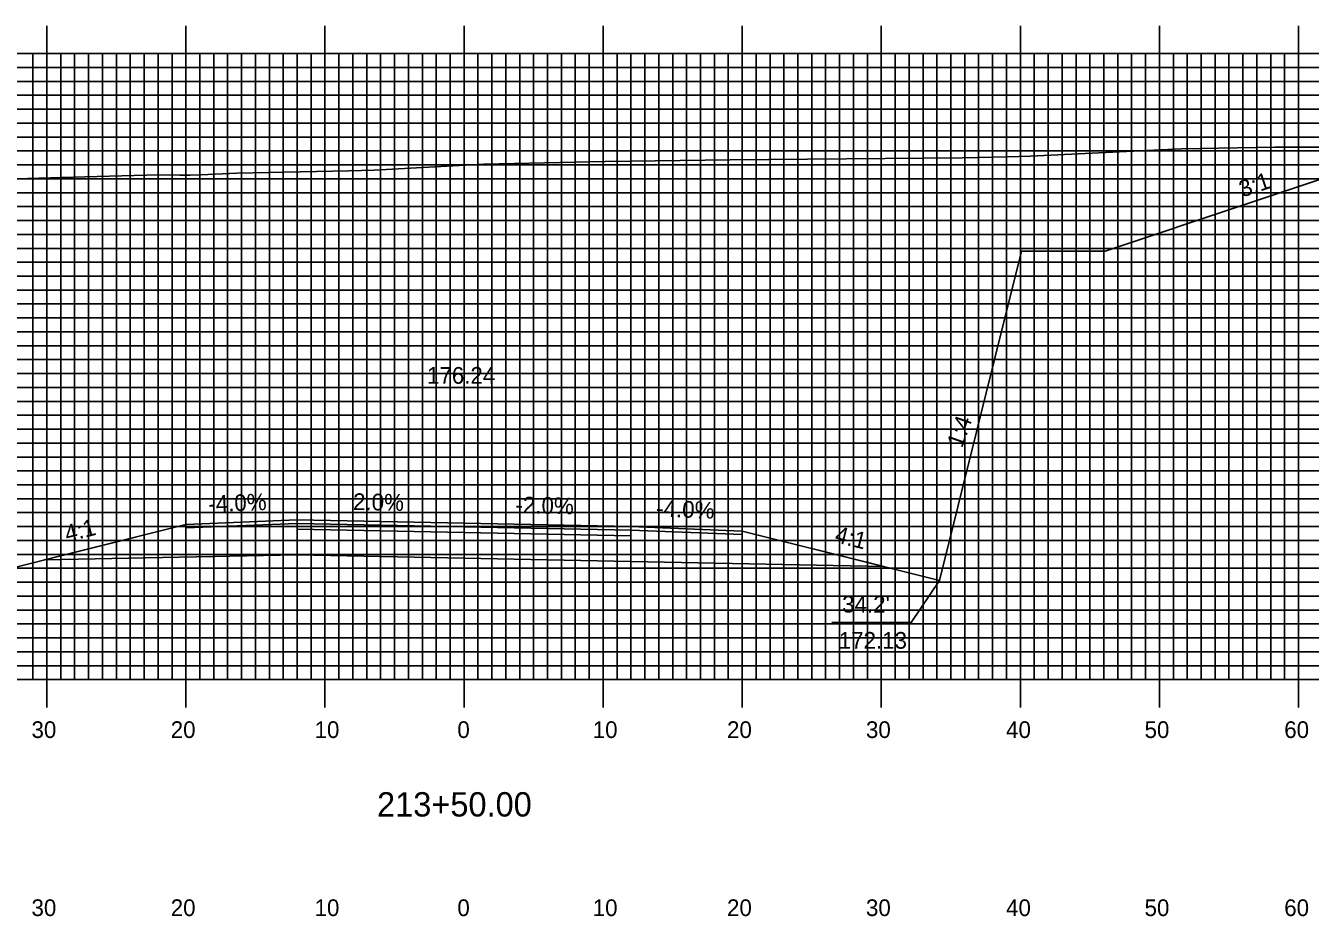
# Model space of a CAD drawing. Extents: x 1795633 to 1795976, y 442591 to 442811.
# Drawn here: x 1795767.4 to 1795859.7, y 442656.6 to 442720.7 of the extents above; entities that cross this region are included whole.
import ezdxf

# ---------------------------------------------------------------- set-up
doc = ezdxf.new("R2010")
doc.units = 0
for name, color, linetype in [('ANNOTATION', 7, 'Continuous'), ('D_Roadway_Centerline', 7, 'Continuous'), ('D_Roadway_Centerline_Text', 7, 'Continuous'), ('D_Roadway_Edge_Shoulder', 7, 'Continuous'), ('D_Roadway_Edge_TW', 7, 'Continuous'), ('D_Roadway_Pavement', 7, 'Continuous'), ('D_Roadway_SlopeLines', 7, 'Continuous'), ('D_Roadway_SubGrade', 7, 'Continuous'), ('H_V ANNOTATION', 7, 'Continuous'), ('MAJOR', 7, 'Continuous'), ('MINOR', 7, 'Continuous'), ('S_Roadway_Centerline', 7, 'Continuous')]:
    doc.layers.add(name, color=color, linetype=linetype)

msp = doc.modelspace()

# ---------------------------------------------------------------- linework, layer by layer
at = {"layer": 'ANNOTATION'}
msp.add_lwpolyline([(1795825.33, 442677.758), (1795831.021, 442677.758), (1795833.053, 442680.798)], dxfattribs=at)
at = {"layer": 'D_Roadway_Edge_Shoulder'}
for points in [[(1795786.879, 442685.142), (1795778.879, 442684.822), (1795778.879, 442684.572), (1795786.879, 442684.892)], [(1795810.879, 442684.662), (1795818.879, 442684.342), (1795818.879, 442684.092), (1795810.879, 442684.412)]]:
    msp.add_lwpolyline(points, close=True, dxfattribs=at)
at = {"layer": 'D_Roadway_Edge_TW'}
msp.add_lwpolyline([(1795786.879, 442684.892), (1795786.879, 442685.142), (1795798.879, 442684.902), (1795810.879, 442684.662), (1795810.879, 442684.412), (1795798.879, 442684.652)], close=True, dxfattribs=at)
at = {"layer": 'D_Roadway_Pavement'}
msp.add_lwpolyline([(1795786.879, 442684.475), (1795786.879, 442684.892), (1795798.879, 442684.652), (1795810.879, 442684.412), (1795810.879, 442683.995), (1795798.879, 442684.235)], close=True, dxfattribs=at)
at = {"layer": 'D_Roadway_SlopeLines'}
msp.add_line((1795833.053, 442680.798), (1795837.071, 442696.871), dxfattribs=at)
for points in [[(1795837.071, 442696.871), (1795838.97, 442704.465), (1795844.97, 442704.465), (1795865.487, 442711.304)], [(1795778.879, 442684.822), (1795764.705, 442681.278)], [(1795818.879, 442684.342), (1795833.053, 442680.798)]]:
    msp.add_lwpolyline(points, dxfattribs=at)
at = {"layer": 'D_Roadway_SubGrade'}
msp.add_lwpolyline([(1795786.879, 442682.642), (1795768.705, 442682.278), (1795778.879, 442684.822), (1795778.879, 442684.572), (1795786.879, 442684.892), (1795798.879, 442684.652), (1795810.879, 442684.412), (1795818.879, 442684.092), (1795818.879, 442684.342), (1795829.053, 442681.798), (1795810.879, 442682.162), (1795798.879, 442682.402)], close=True, dxfattribs=at)
at = {"layer": 'MAJOR'}
for p, q in [((1795768.879, 442720.669), (1795768.879, 442718.665)), ((1795778.879, 442720.669), (1795778.879, 442718.665)), ((1795788.879, 442720.669), (1795788.879, 442718.665)), ((1795798.879, 442720.669), (1795798.879, 442718.665)), ((1795808.879, 442720.669), (1795808.879, 442718.665)), ((1795818.879, 442720.669), (1795818.879, 442718.665)), ((1795828.879, 442720.669), (1795828.879, 442718.665)), ((1795838.879, 442720.669), (1795838.879, 442718.665)), ((1795848.879, 442720.669), (1795848.879, 442718.665)), ((1795858.879, 442720.669), (1795858.879, 442718.665)), ((1795658.879, 442718.665), (1795938.879, 442718.665)), ((1795658.879, 442718.665), (1795938.879, 442718.665)), ((1795768.879, 442673.665), (1795768.879, 442718.665)), ((1795778.879, 442673.665), (1795778.879, 442718.665)), ((1795788.879, 442673.665), (1795788.879, 442718.665)), ((1795798.879, 442673.665), (1795798.879, 442718.665)), ((1795808.879, 442673.665), (1795808.879, 442718.665)), ((1795818.879, 442673.665), (1795818.879, 442718.665)), ((1795828.879, 442673.665), (1795828.879, 442718.665)), ((1795838.879, 442673.665), (1795838.879, 442718.665)), ((1795848.879, 442673.665), (1795848.879, 442718.665)), ((1795858.879, 442673.665), (1795858.879, 442718.665)), ((1795658.879, 442713.665), (1795938.879, 442713.665)), ((1795658.879, 442708.665), (1795938.879, 442708.665)), ((1795658.879, 442703.665), (1795938.879, 442703.665)), ((1795658.879, 442698.665), (1795938.879, 442698.665)), ((1795658.879, 442693.665), (1795938.879, 442693.665)), ((1795658.879, 442688.665), (1795938.879, 442688.665)), ((1795658.879, 442683.665), (1795938.879, 442683.665)), ((1795658.879, 442678.665), (1795938.879, 442678.665)), ((1795658.879, 442673.665), (1795938.879, 442673.665)), ((1795658.879, 442673.665), (1795938.879, 442673.665)), ((1795768.879, 442671.661), (1795768.879, 442673.665)), ((1795778.879, 442671.661), (1795778.879, 442673.665)), ((1795788.879, 442671.661), (1795788.879, 442673.665)), ((1795798.879, 442671.661), (1795798.879, 442673.665)), ((1795808.879, 442671.661), (1795808.879, 442673.665)), ((1795818.879, 442671.661), (1795818.879, 442673.665)), ((1795828.879, 442671.661), (1795828.879, 442673.665)), ((1795838.879, 442671.661), (1795838.879, 442673.665)), ((1795848.879, 442671.661), (1795848.879, 442673.665)), ((1795858.879, 442671.661), (1795858.879, 442673.665))]:
    msp.add_line(p, q, dxfattribs=at)
at = {"layer": 'MINOR'}
for p, q in [((1795767.879, 442673.665), (1795767.879, 442718.665)), ((1795769.879, 442673.665), (1795769.879, 442718.665)), ((1795770.879, 442673.665), (1795770.879, 442718.665)), ((1795771.879, 442673.665), (1795771.879, 442718.665)), ((1795772.879, 442673.665), (1795772.879, 442718.665)), ((1795773.879, 442673.665), (1795773.879, 442718.665)), ((1795774.879, 442673.665), (1795774.879, 442718.665)), ((1795775.879, 442673.665), (1795775.879, 442718.665)), ((1795776.879, 442673.665), (1795776.879, 442718.665)), ((1795777.879, 442673.665), (1795777.879, 442718.665)), ((1795779.879, 442673.665), (1795779.879, 442718.665)), ((1795780.879, 442673.665), (1795780.879, 442718.665)), ((1795781.879, 442673.665), (1795781.879, 442718.665)), ((1795782.879, 442673.665), (1795782.879, 442718.665)), ((1795783.879, 442673.665), (1795783.879, 442718.665)), ((1795784.879, 442673.665), (1795784.879, 442718.665)), ((1795785.879, 442673.665), (1795785.879, 442718.665)), ((1795786.879, 442673.665), (1795786.879, 442718.665)), ((1795787.879, 442673.665), (1795787.879, 442718.665)), ((1795789.879, 442673.665), (1795789.879, 442718.665)), ((1795790.879, 442673.665), (1795790.879, 442718.665)), ((1795791.879, 442673.665), (1795791.879, 442718.665)), ((1795792.879, 442673.665), (1795792.879, 442718.665)), ((1795793.879, 442673.665), (1795793.879, 442718.665)), ((1795794.879, 442673.665), (1795794.879, 442718.665)), ((1795795.879, 442673.665), (1795795.879, 442718.665)), ((1795796.879, 442673.665), (1795796.879, 442718.665)), ((1795797.879, 442673.665), (1795797.879, 442718.665)), ((1795799.879, 442673.665), (1795799.879, 442718.665)), ((1795800.879, 442673.665), (1795800.879, 442718.665)), ((1795801.879, 442673.665), (1795801.879, 442718.665)), ((1795802.879, 442673.665), (1795802.879, 442718.665)), ((1795803.879, 442673.665), (1795803.879, 442718.665)), ((1795804.879, 442673.665), (1795804.879, 442718.665)), ((1795805.879, 442673.665), (1795805.879, 442718.665)), ((1795806.879, 442673.665), (1795806.879, 442718.665)), ((1795807.879, 442673.665), (1795807.879, 442718.665)), ((1795809.879, 442673.665), (1795809.879, 442718.665)), ((1795810.879, 442673.665), (1795810.879, 442718.665)), ((1795811.879, 442673.665), (1795811.879, 442718.665)), ((1795812.879, 442673.665), (1795812.879, 442718.665)), ((1795813.879, 442673.665), (1795813.879, 442718.665)), ((1795814.879, 442673.665), (1795814.879, 442718.665)), ((1795815.879, 442673.665), (1795815.879, 442718.665)), ((1795816.879, 442673.665), (1795816.879, 442718.665)), ((1795817.879, 442673.665), (1795817.879, 442718.665)), ((1795819.879, 442673.665), (1795819.879, 442718.665)), ((1795820.879, 442673.665), (1795820.879, 442718.665)), ((1795821.879, 442673.665), (1795821.879, 442718.665)), ((1795822.879, 442673.665), (1795822.879, 442718.665)), ((1795823.879, 442673.665), (1795823.879, 442718.665)), ((1795824.879, 442673.665), (1795824.879, 442718.665)), ((1795825.879, 442673.665), (1795825.879, 442718.665)), ((1795826.879, 442673.665), (1795826.879, 442718.665)), ((1795827.879, 442673.665), (1795827.879, 442718.665)), ((1795829.879, 442673.665), (1795829.879, 442718.665)), ((1795830.879, 442673.665), (1795830.879, 442718.665)), ((1795831.879, 442673.665), (1795831.879, 442718.665)), ((1795832.879, 442673.665), (1795832.879, 442718.665)), ((1795833.879, 442673.665), (1795833.879, 442718.665)), ((1795834.879, 442673.665), (1795834.879, 442718.665)), ((1795835.879, 442673.665), (1795835.879, 442718.665)), ((1795836.879, 442673.665), (1795836.879, 442718.665)), ((1795837.879, 442673.665), (1795837.879, 442718.665)), ((1795839.879, 442673.665), (1795839.879, 442718.665)), ((1795840.879, 442673.665), (1795840.879, 442718.665)), ((1795841.879, 442673.665), (1795841.879, 442718.665)), ((1795842.879, 442673.665), (1795842.879, 442718.665)), ((1795843.879, 442673.665), (1795843.879, 442718.665)), ((1795844.879, 442673.665), (1795844.879, 442718.665)), ((1795845.879, 442673.665), (1795845.879, 442718.665)), ((1795846.879, 442673.665), (1795846.879, 442718.665)), ((1795847.879, 442673.665), (1795847.879, 442718.665)), ((1795849.879, 442673.665), (1795849.879, 442718.665)), ((1795850.879, 442673.665), (1795850.879, 442718.665)), ((1795851.879, 442673.665), (1795851.879, 442718.665)), ((1795852.879, 442673.665), (1795852.879, 442718.665)), ((1795853.879, 442673.665), (1795853.879, 442718.665)), ((1795854.879, 442673.665), (1795854.879, 442718.665)), ((1795855.879, 442673.665), (1795855.879, 442718.665)), ((1795856.879, 442673.665), (1795856.879, 442718.665)), ((1795857.879, 442673.665), (1795857.879, 442718.665)), ((1795658.879, 442717.665), (1795938.879, 442717.665)), ((1795658.879, 442716.665), (1795938.879, 442716.665)), ((1795658.879, 442715.665), (1795938.879, 442715.665)), ((1795658.879, 442714.665), (1795938.879, 442714.665)), ((1795658.879, 442712.665), (1795938.879, 442712.665)), ((1795658.879, 442711.665), (1795938.879, 442711.665)), ((1795658.879, 442710.665), (1795938.879, 442710.665)), ((1795658.879, 442709.665), (1795938.879, 442709.665)), ((1795658.879, 442707.665), (1795938.879, 442707.665)), ((1795658.879, 442706.665), (1795938.879, 442706.665)), ((1795658.879, 442705.665), (1795938.879, 442705.665)), ((1795658.879, 442704.665), (1795938.879, 442704.665)), ((1795658.879, 442702.665), (1795938.879, 442702.665)), ((1795658.879, 442701.665), (1795938.879, 442701.665)), ((1795658.879, 442700.665), (1795938.879, 442700.665)), ((1795658.879, 442699.665), (1795938.879, 442699.665)), ((1795658.879, 442697.665), (1795938.879, 442697.665)), ((1795658.879, 442696.665), (1795938.879, 442696.665)), ((1795658.879, 442695.665), (1795938.879, 442695.665)), ((1795658.879, 442694.665), (1795938.879, 442694.665)), ((1795658.879, 442692.665), (1795938.879, 442692.665)), ((1795658.879, 442691.665), (1795938.879, 442691.665)), ((1795658.879, 442690.665), (1795938.879, 442690.665)), ((1795658.879, 442689.665), (1795938.879, 442689.665)), ((1795658.879, 442687.665), (1795938.879, 442687.665)), ((1795658.879, 442686.665), (1795938.879, 442686.665)), ((1795658.879, 442685.665), (1795938.879, 442685.665)), ((1795658.879, 442684.665), (1795938.879, 442684.665)), ((1795658.879, 442682.665), (1795938.879, 442682.665)), ((1795658.879, 442681.665), (1795938.879, 442681.665)), ((1795658.879, 442680.665), (1795938.879, 442680.665)), ((1795658.879, 442679.665), (1795938.879, 442679.665)), ((1795658.879, 442677.665), (1795938.879, 442677.665)), ((1795658.879, 442676.665), (1795938.879, 442676.665)), ((1795658.879, 442675.665), (1795938.879, 442675.665)), ((1795658.879, 442674.665), (1795938.879, 442674.665))]:
    msp.add_line(p, q, dxfattribs=at)
at = {"layer": 'S_Roadway_Centerline'}
msp.add_lwpolyline([(1795764.979, 442709.62), (1795771.604, 442709.8), (1795776.044, 442709.925), (1795777.71, 442709.939), (1795778.435, 442709.916), (1795779.196, 442709.921), (1795779.951, 442709.943), (1795782.543, 442710.057), (1795787.083, 442710.167), (1795790.583, 442710.246), (1795792.411, 442710.29), (1795797.213, 442710.553), (1795800.289, 442710.717), (1795809.014, 442710.9), (1795818.023, 442711.018), (1795834.726, 442711.182), (1795837.933, 442711.233), (1795839.576, 442711.287), (1795850.458, 442711.817), (1795857.177, 442711.944), (1795862.64, 442711.931)], dxfattribs=at)

# ---------------------------------------------------------------- texts
at = {"layer": 'ANNOTATION'}
for s, rotation, p in [('3:1', 18.71551, (1795854.847, 442708.315)), ('3:1', 18.71551, (1795854.847, 442708.315)), ('1:4', 70.51601, (1795834.691, 442690.259)), ('-4.0%', 2.29061, (1795780.511, 442685.689)), ('2.0%', 358.85424, (1795790.886, 442685.862)), ('-2.0%', 358.85424, (1795802.565, 442685.628)), ('-4.0%', 357.70939, (1795812.671, 442685.392)), ('4:1', 14.03624, (1795770.328, 442683.545)), ('4:1', 345.96376, (1795825.472, 442683.555))]:
    msp.add_text(s, height=1.2, rotation=rotation, dxfattribs=at).set_placement(p)
for s, p in [("34.2'", (1795826.064, 442678.484)), ('172.13', (1795825.818, 442675.884))]:
    msp.add_text(s, height=1.2, dxfattribs=at).set_placement(p)
at = {"layer": 'D_Roadway_Centerline'}
for s, p in [('C', (1795798.874, 442684.902)), ('L', (1795798.879, 442684.894))]:
    msp.add_text(s, height=0.0146, dxfattribs=at).set_placement(p)
at = {"layer": 'D_Roadway_Centerline_Text'}
msp.add_text('176.24', height=1.2, dxfattribs=at).set_placement((1795796.214, 442694.932))
at = {"layer": 'H_V ANNOTATION'}
for s, height, p in [('30', 1.2, (1795767.776, 442669.465)), ('20', 1.2, (1795777.787, 442669.465)), ('10', 1.2, (1795788.13, 442669.465)), ('0', 1.2, (1795798.397, 442669.465)), ('10', 1.2, (1795808.13, 442669.465)), ('20', 1.2, (1795817.787, 442669.465)), ('30', 1.2, (1795827.776, 442669.465)), ('40', 1.2, (1795837.851, 442669.465)), ('50', 1.2, (1795847.808, 442669.465)), ('60', 1.2, (1795857.851, 442669.465)), ('213+50.00', 1.75, (1795792.621, 442663.821)), ('30', 1.2, (1795767.776, 442656.665)), ('20', 1.2, (1795777.787, 442656.665)), ('10', 1.2, (1795788.13, 442656.665)), ('0', 1.2, (1795798.397, 442656.665)), ('10', 1.2, (1795808.13, 442656.665)), ('20', 1.2, (1795817.787, 442656.665)), ('30', 1.2, (1795827.776, 442656.665)), ('40', 1.2, (1795837.851, 442656.665)), ('50', 1.2, (1795847.808, 442656.665)), ('60', 1.2, (1795857.851, 442656.665))]:
    msp.add_text(s, height=height, dxfattribs=at).set_placement(p)

doc.saveas('drawing.dxf')
